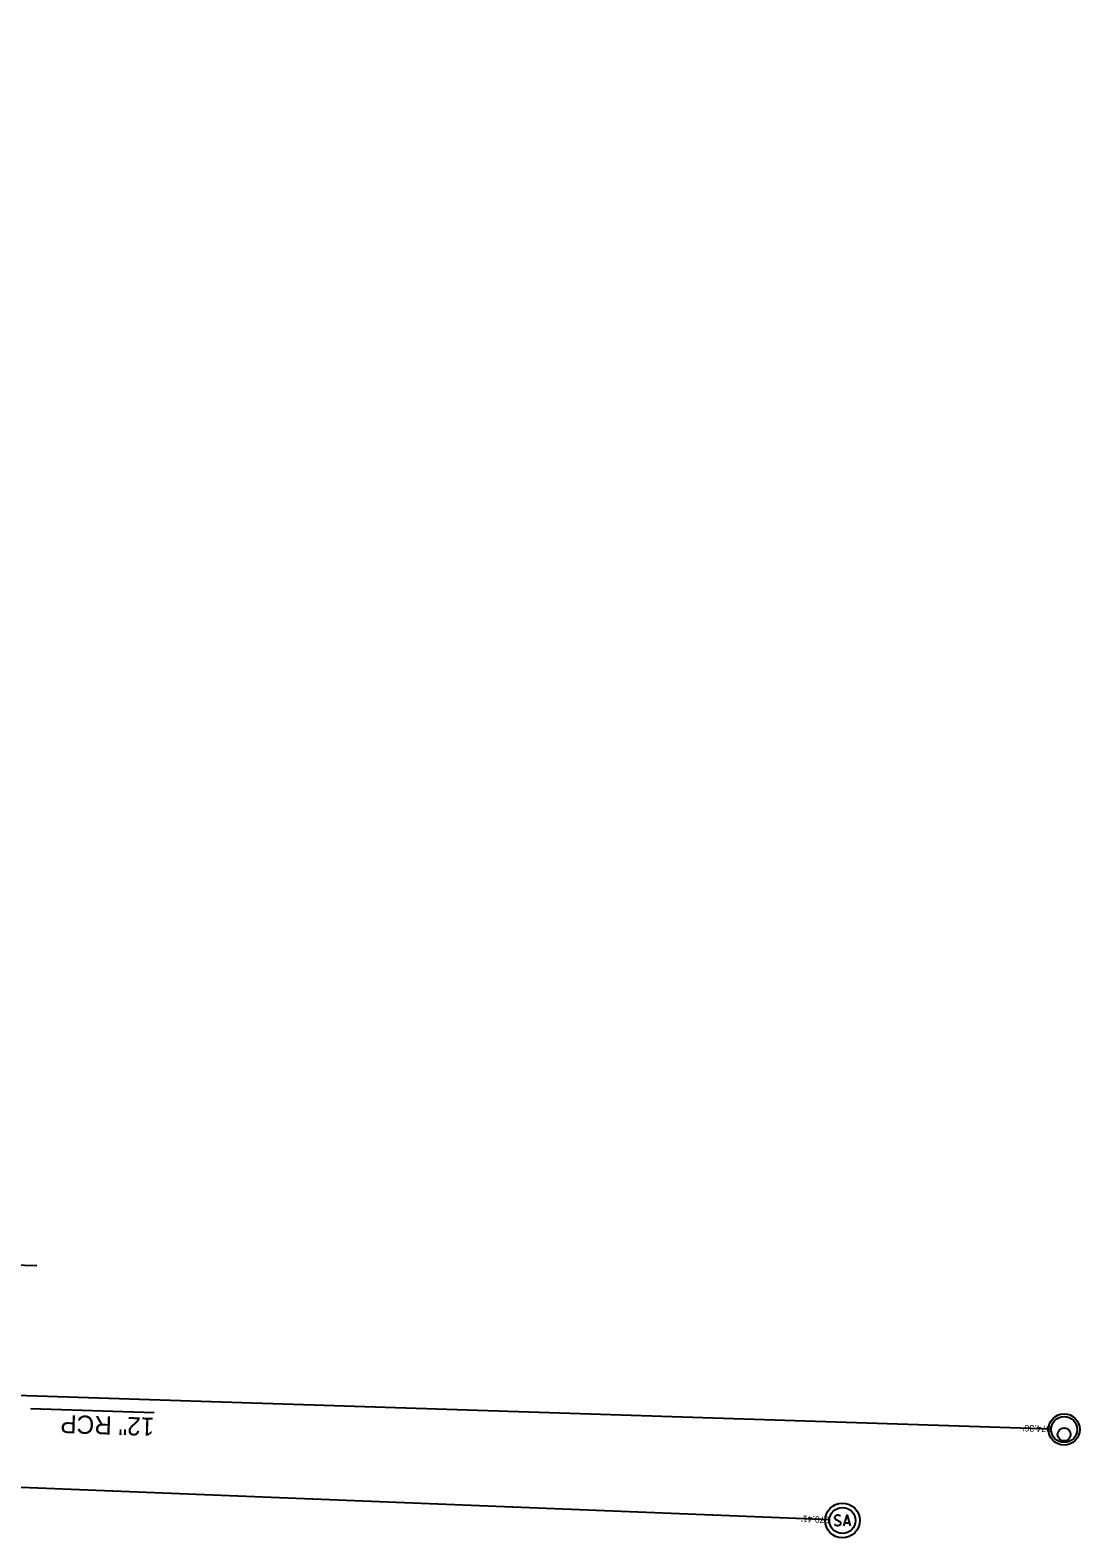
# Model space of a CAD drawing. Extents: x 1380550 to 1381945, y 468927 to 470496.
# Drawn here: x 1381783.2 to 1381944.7, y 470212 to 470443.9 of the extents above; entities that cross this region are included whole.
import ezdxf

# ---------------------------------------------------------------- set-up
doc = ezdxf.new("R2010")
doc.units = 0
for name, color, linetype in [('DR_X_Cells', 7, 'Continuous'), ('DR_X_Storm_Sewer', 7, 'Continuous'), ('DR_X_Text', 7, 'Continuous'), ('GK_Drainage_Nodes', 7, 'Continuous'), ('RW_X_Esmt_General', 7, 'Continuous'), ('SC_Scratch1', 7, 'Continuous'), ('UT_X_Sanitary_Cells', 7, 'Continuous')]:
    doc.layers.add(name, color=color, linetype=linetype)

msp = doc.modelspace()

# ---------------------------------------------------------------- linework, layer by layer
at = {"layer": 'DR_X_Cells'}
for centre, radius in [((1381942.27, 470228.65), 2.42), ((1381942.27, 470228.65), 2), ((1381942.27, 470227.9), 1)]:
    msp.add_circle(centre, radius, dxfattribs=at)
at = {"layer": 'DR_X_Storm_Sewer'}
for p, q in [((1381940.27, 470228.72), (1381649.42, 470238.11)), ((1381906.16, 470214.73), (1381603.06, 470226.96))]:
    msp.add_line(p, q, dxfattribs=at)
at = {"layer": 'DR_X_Text'}
msp.add_line((1381783.25, 470231.88), (1381802.32, 470231.27), dxfattribs=at)
at = {"layer": 'GK_Drainage_Nodes'}
for p, q in [((1381942.27, 470230.65), (1381942.27, 470230.65)), ((1381942.27, 470228.65), (1381942.27, 470228.65)), ((1381942.27, 470228.65), (1381942.27, 470228.65)), ((1381942.27, 470227.9), (1381942.27, 470227.9)), ((1381942.27, 470226.65), (1381942.27, 470226.65)), ((1381908.16, 470216.65), (1381908.16, 470216.65)), ((1381908.16, 470214.65), (1381908.16, 470214.65)), ((1381908.16, 470214.65), (1381908.16, 470214.65)), ((1381908.16, 470214.65), (1381908.16, 470214.65)), ((1381908.16, 470212.65), (1381908.16, 470212.65))]:
    msp.add_line(p, q, dxfattribs=at)
for centre in [(1381942.27, 470228.65), (1381908.16, 470214.65)]:
    msp.add_circle(centre, 2, dxfattribs=at)
at = {"layer": 'RW_X_Esmt_General'}
msp.add_lwpolyline([(1381668.02, 470443.9), (1381652.43, 470257.4), (1381784.26, 470253.87)], dxfattribs=at)
at = {"layer": 'UT_X_Sanitary_Cells'}
for points in [[(1381907.83, 470215.33), (1381907.8, 470215.36), (1381907.76, 470215.38), (1381907.65, 470215.42), (1381907.51, 470215.45), (1381907.41, 470215.45), (1381907.37, 470215.45), (1381907.21, 470215.41), (1381907.07, 470215.33), (1381906.98, 470215.23), (1381906.96, 470215.13), (1381906.96, 470215.06), (1381906.98, 470214.96), (1381907.08, 470214.87), (1381907.78, 470214.49), (1381907.84, 470214.44), (1381907.86, 470214.39), (1381907.89, 470214.31), (1381907.89, 470214.24), (1381907.88, 470214.16), (1381907.86, 470214.11), (1381907.84, 470214.05), (1381907.81, 470214), (1381907.79, 470213.96), (1381907.75, 470213.92), (1381907.71, 470213.9), (1381907.66, 470213.87), (1381907.62, 470213.86), (1381907.51, 470213.85), (1381907.34, 470213.85), (1381907.22, 470213.87), (1381907.06, 470213.96), (1381906.96, 470214.04)], [(1381908.37, 470213.85), (1381908.87, 470215.45), (1381909.36, 470213.85)], [(1381909.24, 470214.22), (1381908.49, 470214.22)]]:
    msp.add_lwpolyline(points, dxfattribs=at)
for radius in [2.67, 2]:
    msp.add_circle((1381908.16, 470214.65), radius, dxfattribs=at)

# ---------------------------------------------------------------- texts
at = {"layer": 'DR_X_Text'}
msp.add_text('12" RCP', height=2.8, rotation=178.1508, dxfattribs=at).set_placement((1381802.36, 470230.44))
at = {"layer": 'SC_Scratch1'}
for s, rotation, p in [("874.36'", 178.1508, (1381940.28, 470229.22)), ("870.41'", 177.6889, (1381906.18, 470215.23))]:
    msp.add_text(s, height=1, rotation=rotation, dxfattribs=at).set_placement(p)

doc.saveas('drawing.dxf')
